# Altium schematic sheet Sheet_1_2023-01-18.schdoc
size 290 x 182 mm
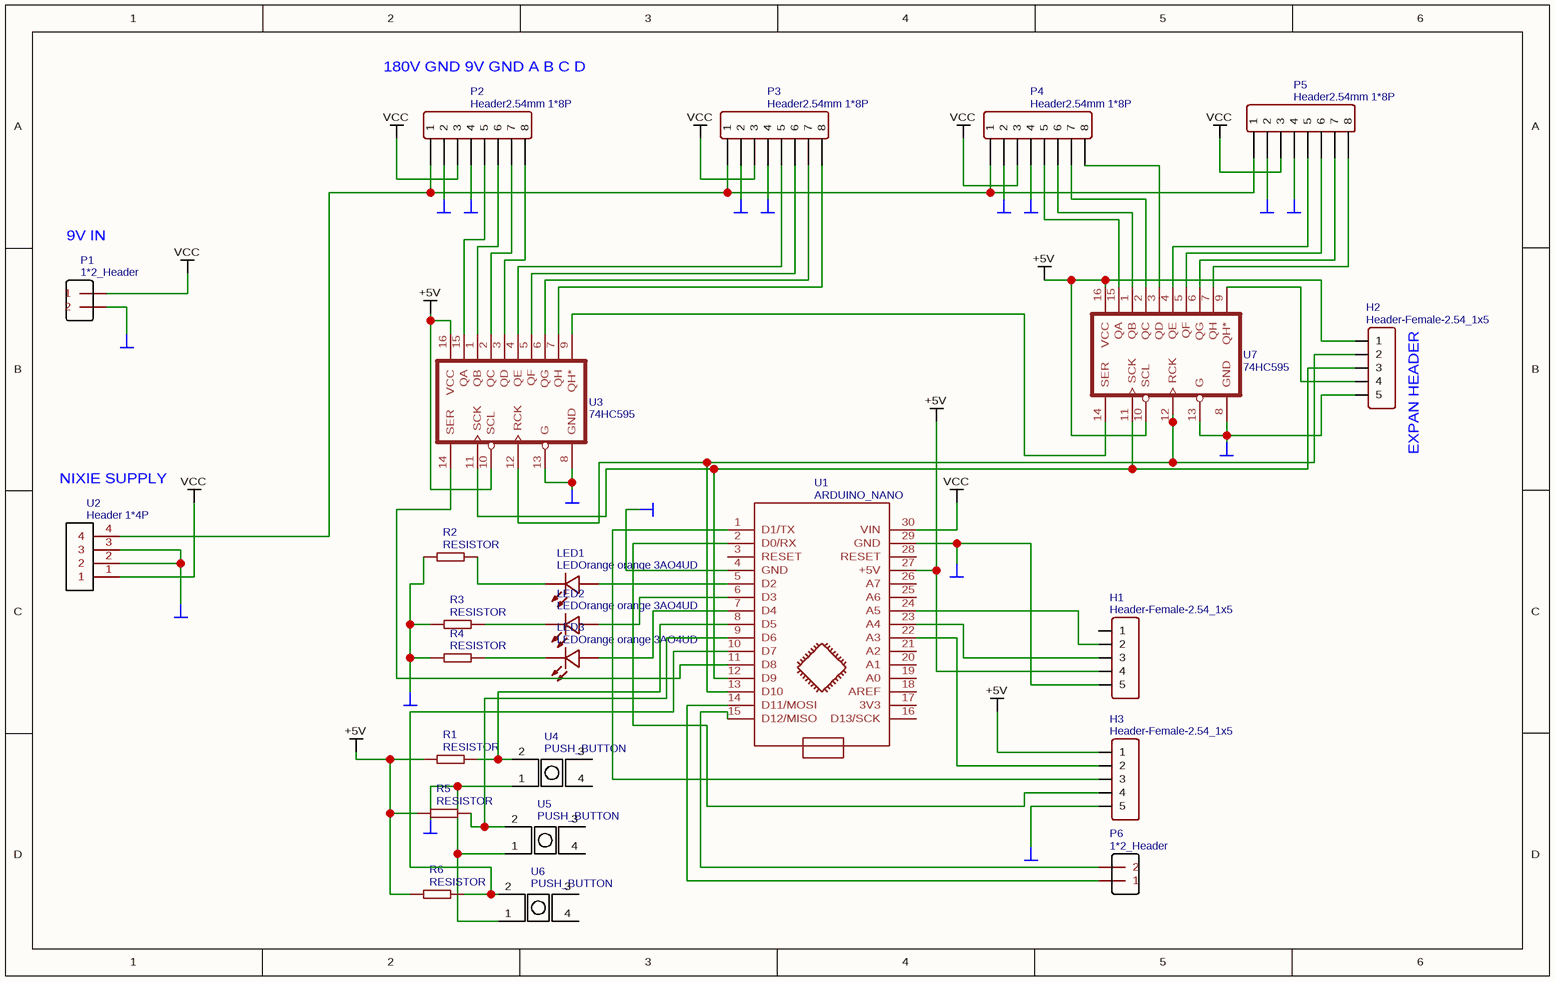
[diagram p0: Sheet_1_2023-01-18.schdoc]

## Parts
H1  Header-Female-2.54_1x5  [HDR-5X1/2.54]
H2  Header-Female-2.54_1x5  [HDR-5X1/2.54]
H3  Header-Female-2.54_1x5  [HDR-5X1/2.54]
LED1  LEDOrange orange 3AO4UD  [LED-3MM]
LED2  LEDOrange orange 3AO4UD  [LED-3MM]
LED3  LEDOrange orange 3AO4UD  [LED-3MM]
P1  1*2_Header  [1*2 HEADER]
P2  Header2.54mm 1*8P  [HDR-8X1/2.54]
P3  Header2.54mm 1*8P  [HDR-8X1/2.54]
P4  Header2.54mm 1*8P  [HDR-8X1/2.54]
P5  Header2.54mm 1*8P  [HDR-8X1/2.54]
P6  1*2_Header  [1*2 HEADER]
R1  RESISTOR  [RTH025W]
R2  RESISTOR  [RTH025W]
R3  RESISTOR  [RTH025W]
R4  RESISTOR  [RTH025W]
R5  RESISTOR  [RTH025W]
R6  RESISTOR  [RTH025W]
U1  ARDUINO_NANO  [ARDUINO_NANO]
U2  Header 1*4P  [HEADER1*4P]
U3  74HC595  [DIL16]
U4  PUSH_BUTTON  [PUSH_BUTTON]
U5  PUSH_BUTTON  [PUSH_BUTTON]
U6  PUSH_BUTTON  [PUSH_BUTTON]
U7  74HC595  [DIL16]

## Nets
+5V: H1.4 H2.1 H3.1 R1.2 R5.2 R6.2 U1.27(+5V) U3.10(SCL) U3.16(VCC) U7.10(SCL) U7.16(VCC)
GND: H1.5 H2.5 H3.5 P1.2 P2.2 P2.4 P3.2 P3.4 P4.2 P4.4 P5.2 P5.4 R2.2 R3.2 R4.2 U1.4(GND) U1.29(GND) U2.2 U2.3 U3.8(GND) U3.13(G) U4.1 U5.1 U6.1 U7.8(GND) U7.13(G)
VCC: P1.1 P2.3 P3.3 P4.3 P5.3 U1.30(VIN) U2.1
NetH1_2: H1.2 U1.24(A5)
NetH1_3: H1.3 U1.23(A4)
NetH2_2: H2.2 U1.13(D10) U3.12(RCK) U7.12(RCK)
NetH2_3: H2.3 U1.12(D9) U3.11(SCK) U7.11(SCK)
NetH2_4: H2.4 U7.9(QH*)
NetH3_2: H3.2 U1.22(A3)
NetH3_3: H3.3 U1.1(D1/TX)
NetH3_4: H3.4 U1.2(D0/RX)
NetLED1_1: LED1.1(A) U1.5(D2)
NetLED1_2: LED1.2(K) R2.1
NetLED2_1: LED2.1(A) U1.6(D3)
NetLED2_2: LED2.2(K) R3.1
NetLED3_1: LED3.1(A) U1.7(D4)
NetLED3_2: LED3.2(K) R4.1
NetP2_1: P2.1 P3.1 P4.1 P5.1 U2.4
NetP2_5: P2.5 U3.15(QA)
NetP2_6: P2.6 U3.1(QB)
NetP2_7: P2.7 U3.2(QC)
NetP2_8: P2.8 U3.3(QD)
NetP3_5: P3.5 U3.4(QE)
NetP3_6: P3.6 U3.5(QF)
NetP3_7: P3.7 U3.6(QG)
NetP3_8: P3.8 U3.7(QH)
NetP4_5: P4.5 U7.15(QA)
NetP4_6: P4.6 U7.1(QB)
NetP4_7: P4.7 U7.2(QC)
NetP4_8: P4.8 U7.3(QD)
NetP5_5: P5.5 U7.4(QE)
NetP5_6: P5.6 U7.5(QF)
NetP5_7: P5.7 U7.6(QG)
NetP5_8: P5.8 U7.7(QH)
NetP6_1: P6.1 U1.14(D11/MOSI)
NetP6_2: P6.2 U1.15(D12/MISO)
NetR1_1: R1.1 U1.8(D5) U4.2
NetR5_1: R5.1 U1.9(D6) U5.2
NetR6_1: R6.1 U1.10(D7) U6.2
NetU1_11: U1.11(D8) U3.14(SER)
NetU3_9: U3.9(QH*) U7.14(SER)

Not connected (* = marked no-connect by the designer): H1 1; U1 3(RESET) 16(D13/SCK) 17(3V3) 18(AREF) 19(A0) 20(A1) 21(A2) 25(A6) 26(A7) 28(RESET); U4 3 4; U5 3 4; U6 3 4

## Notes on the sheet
- 180V GND 9V GND A B C D
- (near P1) 9V IN
- (near H2) EXPAN HEADER
- (near U2) NIXIE SUPPLY

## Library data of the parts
H1-H3 = Header-Female-2.54_1x5: BOM_Manufacturer: BOOMELE; BOM_Manufacturer Part: 2.54mm 1*5p Female header; Contributor: LCSC
LED1-LED3 = LEDOrange orange 3AO4UD: BOM_Manufacturer: KENTO; Contributor: LCSC
P1 P6 = 1*2_Header: Contributor: Psychokiller1888
P2-P5 = Header2.54mm 1*8P: BOM_Manufacturer: ReliaPro
R1-R6 = RESISTOR: Contributor: DangerousPrototype
U1 = ARDUINO_NANO: sourceId: KGSeAWhDB
U2 = Header 1*4P: BOM_Manufacturer Part: New SchematicLib; Contributor: hardstylzgaming
U3 U7 = 74HC595: Contributor: SparkFun; sourceId: CIUtrpnzx
U4-U6 = PUSH_BUTTON: Contributor: lukasztolak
